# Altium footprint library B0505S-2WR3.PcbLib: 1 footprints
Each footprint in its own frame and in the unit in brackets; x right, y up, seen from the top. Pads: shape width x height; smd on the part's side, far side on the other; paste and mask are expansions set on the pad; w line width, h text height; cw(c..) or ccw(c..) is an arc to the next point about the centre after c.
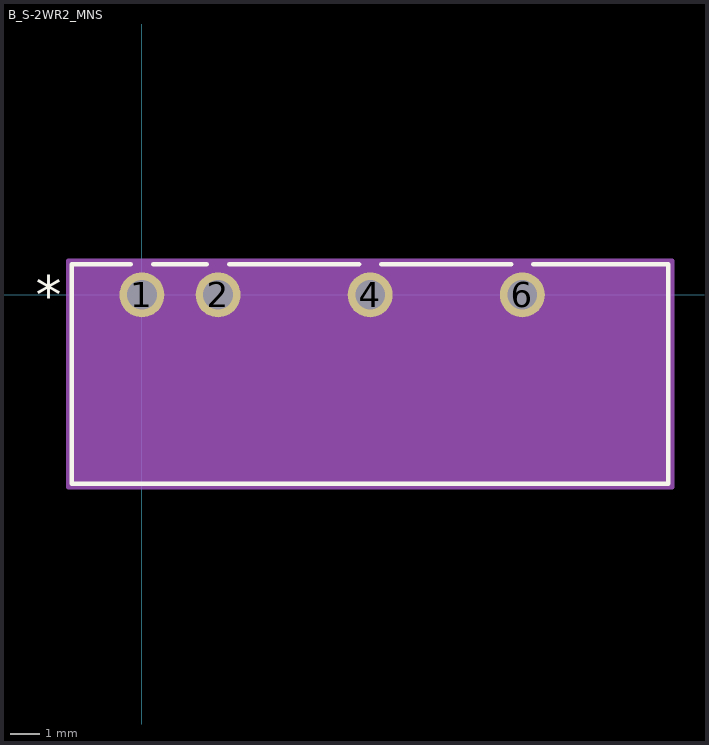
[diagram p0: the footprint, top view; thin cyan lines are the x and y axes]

## B_S-2WR2_MNS [mil]
pads (4):
  round 59 hole 39 paste-29.5 mask+0: 1(0,0) 2(100,0) 4(300,0) 6(500,0)
Top Overlay:
  lines w6: -14.65,40 -92,40 -92,-248 692,-248 692,40 514.65,40 ; 14.65,40 85.35,40 ; 114.65,40 285.35,40 ; 314.65,40 485.35,40
  text "*" at -139.5,-25 h50
  text ".Designator" at 162.5,-129 h50
Mechanical 13:
  lines w1: -87,-243 687,-243 687,35 -87,35 -87,-243
  text ".Designator" at 162.5,-129 h50
  text "*" at -89.5,-25 h50
Mechanical 15:
  region: 697,-253 -97,-253 -97,45 697,45
  lines w6: -97,-253 -97,45 697,45 697,-253 -97,-253
3D body "B_S-2WR2_MNS.step": height 400, standoff -215.98, extent -137.01,-139.02 637.01,139.02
